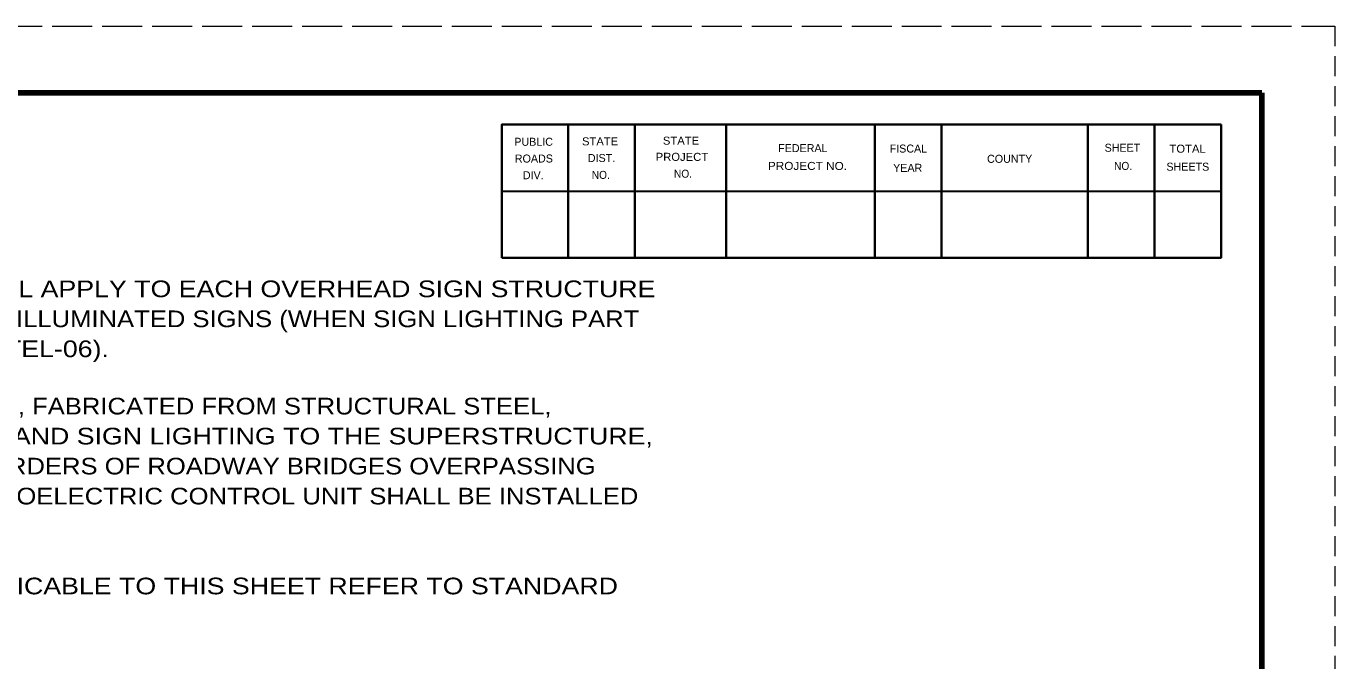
# Model space of a CAD drawing. Extents: x -68 to 612, y -58 to 382.
# Drawn here: x 416 to 612.4, y 286.9 to 382.2 of the extents above; entities that cross this region are included whole.
import ezdxf

# ---------------------------------------------------------------- set-up
doc = ezdxf.new("R2010")
doc.units = 0
doc.linetypes.add('LONG_DASHED', pattern=[7.5, 6, -1.5])
doc.linetypes.add('MEDIUM_DASHED', pattern=[4.5, 3, -1.5])
doc.layers.add('1', color=7, linetype='Continuous', lineweight=53)
doc.layers.add('61', color=7, linetype='Continuous', lineweight=35)

msp = doc.modelspace()

# ---------------------------------------------------------------- linework, layer by layer
at = {"layer": '1', "linetype": 'MEDIUM_DASHED', "lineweight": 13}
msp.add_line((612.409, 382.166), (612.389, -57.854), dxfattribs=at)
at = {"layer": '61', "linetype": 'LONG_DASHED', "lineweight": 13}
msp.add_line((-67.611, 382.166), (612.409, 382.166), dxfattribs=at)
at = {"layer": '61', "lineweight": 158}
msp.add_line((601.429, 372.166), (601.449, -47.874), dxfattribs=at)
at = {"layer": '61'}
for p, q in [((497.349, 367.406), (497.349, 347.406)), ((507.349, 367.406), (507.349, 347.406)), ((521.029, 367.406), (521.029, 347.406)), ((543.349, 367.406), (543.349, 347.406)), ((553.349, 367.406), (553.349, 347.406)), ((575.329, 367.426), (575.329, 347.426)), ((585.329, 367.426), (585.329, 347.426)), ((595.349, 357.386), (487.329, 357.406))]:
    msp.add_line(p, q, dxfattribs=at)
at = {"layer": '61', "lineweight": 158}
msp.add_lwpolyline([(601.429, 372.166), (-37.611, 372.166), (-37.611, -47.854)], dxfattribs=at)
at = {"layer": '61'}
for points in [[(595.329, 367.426), (487.349, 367.406), (487.349, 347.406)], [(595.329, 367.426), (595.329, 347.426), (487.349, 347.406)]]:
    msp.add_lwpolyline(points, dxfattribs=at)

# ---------------------------------------------------------------- texts
at = {"layer": '1'}
for s, width, p in [('DETAILS OF THIS SHEET SHALL APPLY TO EACH OVERHEAD SIGN STRUCTURE', 1.2, (355.053, 341.506)), ('THAT SUPPORTS EXTERNALLY ILLUMINATED SIGNS (WHEN SIGN LIGHTING PART', 1.15, (355.053, 337.006)), ('OF ROADWAY LIGHTING SEE TEL-06).', 1.2, (355.053, 332.506)), ('WHERE SPECIAL SIGN MOUNTS, FABRICATED FROM STRUCTURAL STEEL,', 1.15, (354.908, 323.909)), ('ARE USED TO ATTACH SIGNS AND SIGN LIGHTING TO THE SUPERSTRUCTURE,', 1.2, (354.908, 319.409)), ('PARAPET WALLS, OR PLATE GIRDERS OF ROADWAY BRIDGES OVERPASSING', 1.15, (354.908, 314.909)), ('THE SIGNED ROUTE, THE PHOTOELECTRIC CONTROL UNIT SHALL BE INSTALLED', 1.15, (354.908, 310.409)), ('FOR ADDITIONAL NOTES APPLICABLE TO THIS SHEET REFER TO STANDARD', 1.2, (354.565, 296.92))]:
    msp.add_text(s, height=2.5, dxfattribs=dict(at, width=width)).set_placement(p)
at = {"layer": '61'}
for s, rotation, p in [('PUBLIC', 0.033, (489.244, 364.221)), ('FEDERAL', 0.007, (528.849, 363.266)), ('FISCAL', 359.942, (545.589, 363.206)), ('SHEET', 0.059, (577.849, 363.326)), ('ROADS', 0.124, (489.324, 361.701)), ('DIST.', 0.056, (500.284, 361.781)), ('YEAR', 0.105, (546.109, 360.306)), ('COUNTY', 0.069, (560.209, 361.666)), ('SHEETS', 359.959, (587.129, 360.486)), ('DIV.', 359.932, (490.524, 359.201))]:
    msp.add_text(s, height=1.201, rotation=rotation, dxfattribs=at).set_placement(p)
for s, rotation, width, p in [('STATE', 0.059, 1.05, (499.404, 364.281)), ('STATE', 0.059, 1.05, (511.549, 364.386)), ('TOTAL', 359.926, 1.05, (587.589, 363.186)), ('PROJECT', 359.908, 1.05, (510.469, 361.966)), ('PROJECT NO.', 359.922, 1.1, (527.309, 360.606)), ('NO.', 359.852, 0.95, (579.269, 360.606)), ('NO.', 359.852, 0.95, (500.864, 359.261)), ('NO.', 0.225, 0.95, (513.209, 359.426))]:
    msp.add_text(s, height=1.201, rotation=rotation, dxfattribs=dict(at, width=width)).set_placement(p)

doc.saveas('drawing.dxf')
